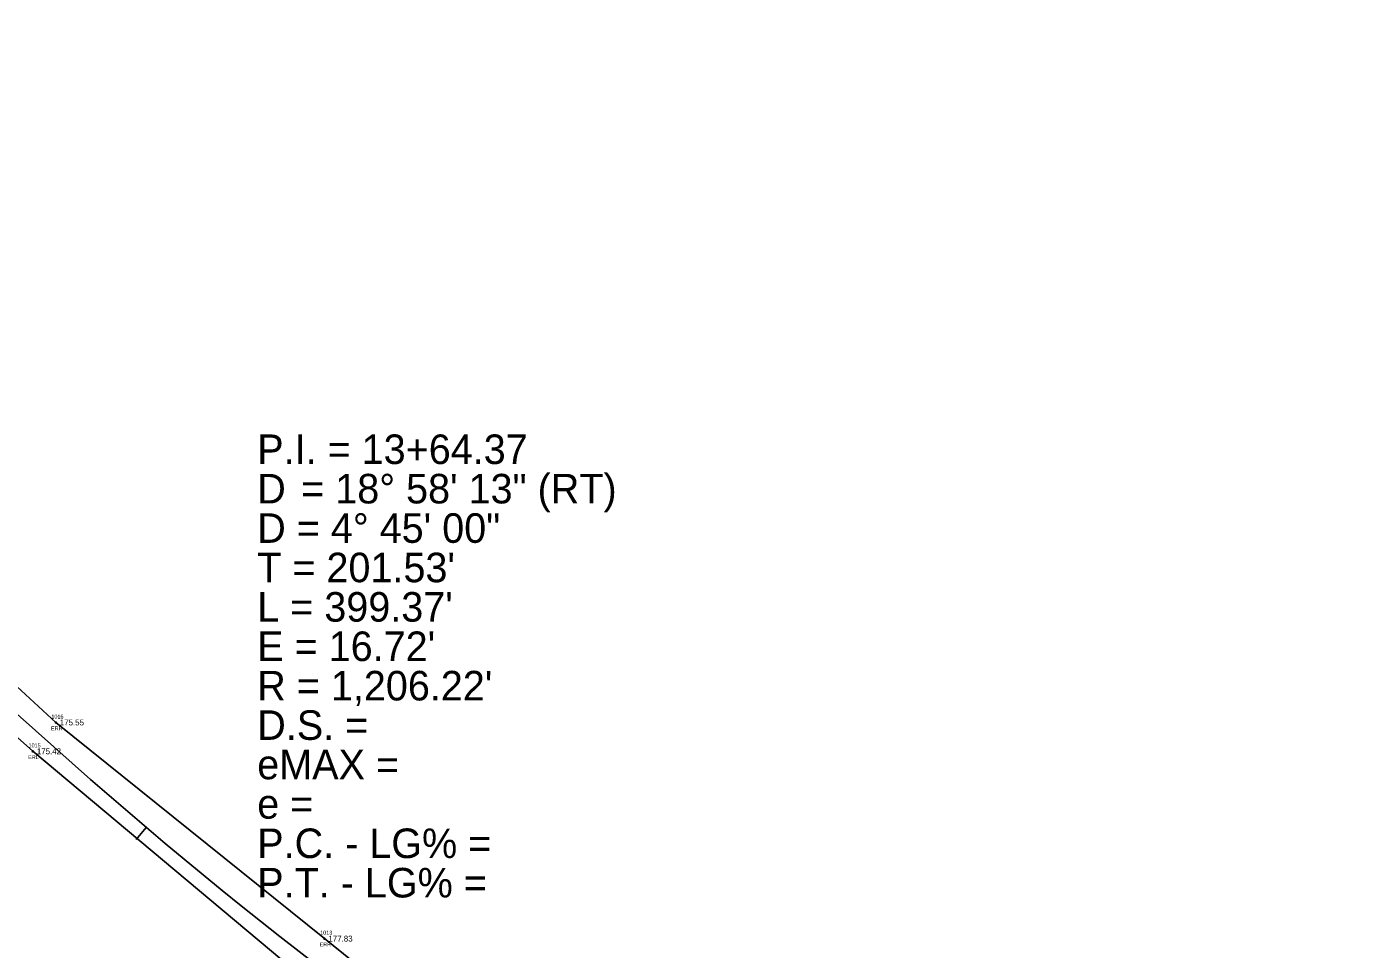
# Model space of a CAD drawing. Extents: x 1970735 to 1971583, y 794736 to 795766.
# Drawn here: x 1971210.6 to 1971550.5, y 795021.9 to 795256 of the extents above; entities that cross this region are included whole.
import ezdxf

# ---------------------------------------------------------------- set-up
doc = ezdxf.new("R2010")
doc.units = 0
for name, color, linetype in [('RD_EX_Road', 7, 'Continuous'), ('RD_EX_Road_txCode', 7, 'Continuous'), ('RD_EX_TX_Road_ELEV', 7, 'Continuous'), ('RD_HC_Cl', 7, 'Continuous'), ('RD_HC_Data', 7, 'Continuous'), ('RD_HC_Data_Tic', 7, 'Continuous'), ('RD_SMD_Locator', 7, 'Continuous')]:
    doc.layers.add(name, color=color, linetype=linetype)

msp = doc.modelspace()

# ---------------------------------------------------------------- linework, layer by layer
at = {"layer": 'RD_EX_Road'}
for points in [[(1971550.5, 794861.13), (1971472.2, 794904.32), (1971401.49, 794943.08), (1971346.58, 794975.73), (1971286.05, 795024.56), (1971217.92, 795079.41), (1971172.76, 795121.06), (1971082.31, 795221.27), (1971017.96, 795288.13), (1970931.75, 795387.33), (1970878.11, 795452.95), (1970856.35, 795489.48), (1970840.29, 795529.45), (1970827.57, 795574.31), (1970814.81, 795635.62), (1970805.04, 795696.13), (1970791.39, 795763.83)], [(1971543.68, 794851.6), (1971507.7, 794872.08), (1971504.76, 794847.96), (1971494.98, 794846.56), (1971488.18, 794883), (1971469.72, 794893.79), (1971395.92, 794934.76), (1971339.47, 794967.38), (1971278.34, 795016.59), (1971212.1, 795072.1), (1971165.04, 795113.96), (1971074.42, 795213.48), (1971010.42, 795281.48), (1970922.49, 795383.19), (1970882.25, 795365.41), (1970854.66, 795404.07), (1970871.45, 795443.76), (1970844.39, 795483.83), (1970828.93, 795526.65), (1970817.76, 795568.61), (1970806.82, 795600.57), (1970787.72, 795602.49), (1970770.58, 795591.56)]]:
    msp.add_lwpolyline(points, dxfattribs=at)
at = {"layer": 'RD_HC_Cl'}
msp.add_arc((1972021.16, 795972.61), 1206.22, 221.98645, 240.95681, dxfattribs=at)
at = {"layer": 'RD_HC_Data_Tic'}
msp.add_line((1971240.85, 795052.77), (1971238.26, 795049.72), dxfattribs=at)
at = {"layer": 'RD_SMD_Locator'}
for centre in [(1971217.92, 795079.41), (1971212.1, 795072.1), (1971286.05, 795024.56)]:
    msp.add_circle(centre, 0.15, dxfattribs=at)

# ---------------------------------------------------------------- texts
at = {"layer": 'RD_EX_Road_txCode'}
for s, p in [('1016', (1971216.79, 795080.41)), ('ERR', (1971216.69, 795077.41)), ('1015', (1971211, 795073.1)), ('ERL', (1971210.89, 795070.1)), ('1013', (1971284.95, 795025.56)), ('ERR', (1971284.82, 795022.56))]:
    msp.add_text(s, height=1, dxfattribs=at).set_placement(p)
at = {"layer": 'RD_EX_TX_Road_ELEV'}
for s, p in [('175.55', (1971218.92, 795078.66)), ('175.42', (1971213.1, 795071.35)), ('177.83', (1971287.05, 795023.81))]:
    msp.add_text(s, height=1.5, dxfattribs=at).set_placement(p)
at = {"layer": 'RD_HC_Data'}
for s, p in [('P.I. = 13+64.37', (1971269, 795145)), ('D', (1971269, 795135)), ('    = 18%%d 58\' 13" (RT)', (1971269, 795135)), ('D = 4%%d 45\' 00"', (1971269, 795125)), ("T = 201.53'", (1971269, 795115)), ("L = 399.37'", (1971269, 795105)), ("E = 16.72'", (1971269, 795095)), ("R = 1,206.22'", (1971269, 795085)), ('D.S. = ', (1971269, 795075)), ('eMAX = ', (1971269, 795065)), ('e = ', (1971269, 795055)), ('P.C. - LG% = ', (1971269, 795045)), ('P.T. - LG% = ', (1971269, 795035))]:
    msp.add_text(s, height=7.5, dxfattribs=at).set_placement(p)

doc.saveas('drawing.dxf')
